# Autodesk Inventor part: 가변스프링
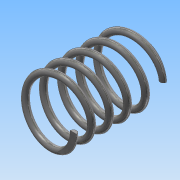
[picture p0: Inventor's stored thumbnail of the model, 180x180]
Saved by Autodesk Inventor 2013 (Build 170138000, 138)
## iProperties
Created: 2017-12
Part Number: 가변스프링
Material: 스테인리스강
Document SubType Name: Modeling
Designer: Administrator
Density: 8.08 g/cm^3
Mass: 7.06913 g
Surface Area: 17.7406 cm^2
Volume: 0.874892 cm^3
Author: Administrator
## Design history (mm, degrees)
sketch "스케치1"
  geometry: L1 (9, 0)-(0, 0); L2 (0, 0)-(0, 28.5); L3 (0, 28.5)-(9, 28.5); C1 r 1 at (9, 0)
  constraints: 6 end point, 1 centre point, 1 coincident, 1 horizontal, 1 parallel, 1 perpendicular
  dimensions: "d0" = 28.5 distance of L1.end L2.end (derived); "d1" = 9 distance of L2.end L3.end; "d2" = 9 distance of L1.start L1.end; "d3" = 2 diameter of C1
feature "코일1" sketch "스케치1" pitch "d4" = 10; turns "d6" = 5; dims "d5" = 28.5 (= d0), "d7" = 0, angle "d8" = 90 deg, angle "d9" = 90 deg, "d10" = 0, "d11" = 0
sketch "스케치2"
  geometry: L1 (28.5, 15)-(0, 15); L2 (0, 15)-(0, -15); L3 (0, -15)-(28.5, -15); L4 (28.5, -15)-(28.5, 15); 2 further points
  constraints: 8 end point, 2 parallel, 1 coincident, 1 horizontal, 1 midpoint, 1 perpendicular
  dimensions: "d12" = 28.5 distance of L2.end L3.end (derived); "d14" = 30 distance of L3.end L1.start
extrude "돌출1" sketch "스케치2" stored distance "d15" = 0; taper "d16" = 0 deg
node "솔리드1"
